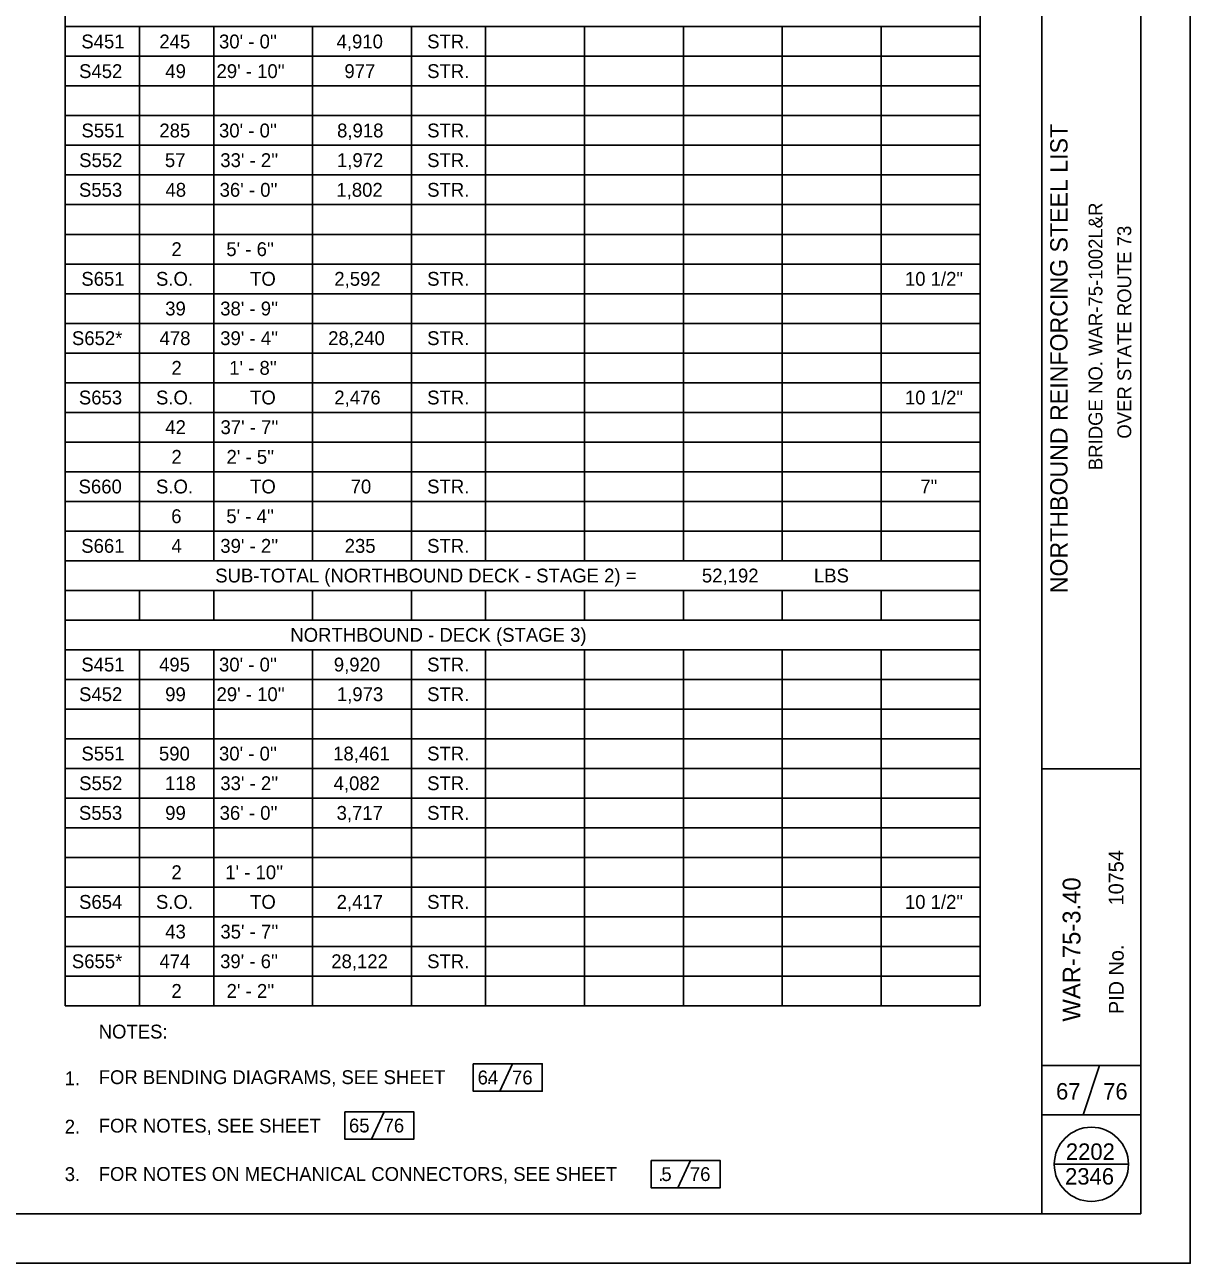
# Model space of a CAD drawing. Extents: x 1485751 to 1485785, y 230696.6 to 230718.6.
# Drawn here: x 1485773.25 to 1485785.03, y 230696.64 to 230709.16 of the extents above; entities that cross this region are included whole.
import ezdxf

# ---------------------------------------------------------------- set-up
doc = ezdxf.new("R2010")
doc.units = 0
for name, color, linetype in [('BR_P_Gen_Text', 7, 'Continuous'), ('BR_P_Sub_Text', 7, 'Continuous'), ('SH_Border', 7, 'Continuous'), ('SH_Cut_Line', 7, 'Continuous'), ('SH_Data', 7, 'Continuous'), ('TX_P_Misc', 7, 'Continuous')]:
    doc.layers.add(name, color=color, linetype=linetype)

msp = doc.modelspace()

# ---------------------------------------------------------------- linework, layer by layer
at = {"layer": 'BR_P_Gen_Text'}
for p, q in [((1485778.18, 230698.658), (1485778.052, 230698.38)), ((1485776.882, 230698.172), (1485776.753, 230697.894)), ((1485779.978, 230697.681), (1485779.85, 230697.403))]:
    msp.add_line(p, q, dxfattribs=at)
for points in [[(1485777.783, 230698.658), (1485778.48, 230698.658), (1485778.48, 230698.38), (1485777.783, 230698.38)], [(1485777.783, 230698.658), (1485778.48, 230698.658), (1485778.48, 230698.38), (1485777.783, 230698.38)], [(1485776.485, 230698.172), (1485777.181, 230698.172), (1485777.181, 230697.894), (1485776.485, 230697.894)], [(1485776.485, 230698.172), (1485777.181, 230698.172), (1485777.181, 230697.894), (1485776.485, 230697.894)], [(1485779.582, 230697.681), (1485780.278, 230697.681), (1485780.278, 230697.403), (1485779.582, 230697.403)], [(1485779.582, 230697.681), (1485780.278, 230697.681), (1485780.278, 230697.403), (1485779.582, 230697.403)]]:
    msp.add_lwpolyline(points, close=True, dxfattribs=at)
at = {"layer": 'SH_Border'}
for p, q in [((1485783.533, 230697.141), (1485783.533, 230718.141)), ((1485783.533, 230697.141), (1485783.533, 230718.141)), ((1485783.533, 230697.141), (1485783.533, 230718.141)), ((1485783.533, 230701.641), (1485784.533, 230701.641)), ((1485783.533, 230701.641), (1485784.533, 230701.641)), ((1485783.533, 230701.641), (1485784.533, 230701.641)), ((1485783.533, 230698.641), (1485784.533, 230698.641)), ((1485783.95, 230698.141), (1485784.116, 230698.641)), ((1485783.533, 230698.141), (1485784.533, 230698.141))]:
    msp.add_line(p, q, dxfattribs=at)
msp.add_lwpolyline([(1485753.033, 230718.141), (1485784.533, 230718.141), (1485784.533, 230697.141), (1485753.033, 230697.141)], close=True, dxfattribs=at)
at = {"layer": 'SH_Cut_Line'}
msp.add_lwpolyline([(1485751.033, 230718.641), (1485785.033, 230718.641), (1485785.033, 230696.641), (1485751.033, 230696.641)], close=True, dxfattribs=at)
at = {"layer": 'SH_Data'}
msp.add_line((1485783.658, 230697.641), (1485784.408, 230697.641), dxfattribs=at)
msp.add_line((1485783.658, 230697.641), (1485784.408, 230697.641), dxfattribs=at)
msp.add_line((1485783.658, 230697.641), (1485784.408, 230697.641), dxfattribs=at)
msp.add_circle((1485784.033, 230697.641), 0.375, dxfattribs=at)
at = {"layer": 'TX_P_Misc'}
for p, q in [((1485773.658, 230717.394), (1485773.658, 230699.244)), ((1485782.908, 230717.394), (1485782.908, 230699.244)), ((1485773.658, 230709.144), (1485782.908, 230709.144)), ((1485774.408, 230709.144), (1485774.408, 230703.744)), ((1485775.158, 230709.144), (1485775.158, 230703.744)), ((1485776.158, 230709.144), (1485776.158, 230703.744)), ((1485777.158, 230709.144), (1485777.158, 230703.744)), ((1485777.908, 230709.144), (1485777.908, 230703.744)), ((1485778.908, 230709.144), (1485778.908, 230703.744)), ((1485779.908, 230709.144), (1485779.908, 230703.744)), ((1485780.908, 230709.144), (1485780.908, 230703.744)), ((1485781.908, 230709.144), (1485781.908, 230703.744)), ((1485773.658, 230708.844), (1485782.908, 230708.844)), ((1485773.658, 230708.544), (1485782.908, 230708.544)), ((1485773.658, 230708.244), (1485782.908, 230708.244)), ((1485773.658, 230707.944), (1485782.908, 230707.944)), ((1485773.658, 230707.644), (1485782.908, 230707.644)), ((1485773.658, 230707.344), (1485782.908, 230707.344)), ((1485773.658, 230707.044), (1485782.908, 230707.044)), ((1485773.658, 230706.744), (1485782.908, 230706.744)), ((1485773.658, 230706.444), (1485782.908, 230706.444)), ((1485773.658, 230706.144), (1485782.908, 230706.144)), ((1485773.658, 230705.844), (1485782.908, 230705.844)), ((1485773.658, 230705.544), (1485782.908, 230705.544)), ((1485773.658, 230705.244), (1485782.908, 230705.244)), ((1485773.658, 230704.944), (1485782.908, 230704.944)), ((1485773.658, 230704.644), (1485782.908, 230704.644)), ((1485773.658, 230704.344), (1485782.908, 230704.344)), ((1485773.658, 230704.044), (1485782.908, 230704.044)), ((1485773.658, 230703.744), (1485782.908, 230703.744)), ((1485773.658, 230703.444), (1485782.908, 230703.444)), ((1485774.408, 230703.444), (1485774.408, 230703.144)), ((1485775.158, 230703.444), (1485775.158, 230703.144)), ((1485776.158, 230703.444), (1485776.158, 230703.144)), ((1485777.158, 230703.444), (1485777.158, 230703.144)), ((1485777.908, 230703.444), (1485777.908, 230703.144)), ((1485778.908, 230703.444), (1485778.908, 230703.144)), ((1485779.908, 230703.444), (1485779.908, 230703.144)), ((1485780.908, 230703.444), (1485780.908, 230703.144)), ((1485781.908, 230703.444), (1485781.908, 230703.144)), ((1485773.658, 230703.144), (1485782.908, 230703.144)), ((1485773.658, 230702.844), (1485782.908, 230702.844)), ((1485774.408, 230702.844), (1485774.408, 230699.244)), ((1485775.158, 230702.844), (1485775.158, 230699.244)), ((1485776.158, 230702.844), (1485776.158, 230699.244)), ((1485777.158, 230702.844), (1485777.158, 230699.244)), ((1485777.908, 230702.844), (1485777.908, 230699.244)), ((1485778.908, 230702.844), (1485778.908, 230699.244)), ((1485779.908, 230702.844), (1485779.908, 230699.244)), ((1485780.908, 230702.844), (1485780.908, 230699.244)), ((1485781.908, 230702.844), (1485781.908, 230699.244)), ((1485773.658, 230702.544), (1485782.908, 230702.544)), ((1485773.658, 230702.244), (1485782.908, 230702.244)), ((1485773.658, 230701.944), (1485782.908, 230701.944)), ((1485773.658, 230701.644), (1485782.908, 230701.644)), ((1485773.658, 230701.344), (1485782.908, 230701.344)), ((1485773.658, 230701.044), (1485782.908, 230701.044)), ((1485773.658, 230700.744), (1485782.908, 230700.744)), ((1485773.658, 230700.444), (1485782.908, 230700.444)), ((1485773.658, 230700.144), (1485782.908, 230700.144)), ((1485773.658, 230699.844), (1485782.908, 230699.844)), ((1485773.658, 230699.544), (1485782.908, 230699.544)), ((1485773.658, 230699.244), (1485782.908, 230699.244))]:
    msp.add_line(p, q, dxfattribs=at)

# ---------------------------------------------------------------- texts
at = {"layer": 'BR_P_Gen_Text'}
for s, p in [('64', (1485777.827, 230698.449)), ('76', (1485778.175, 230698.449)), ('65', (1485776.526, 230697.963)), ('76', (1485776.876, 230697.963)), ('5', (1485779.685, 230697.472)), ('76', (1485779.973, 230697.472))]:
    msp.add_text(s, height=0.14, dxfattribs=at).set_placement(p)
at = {"layer": 'BR_P_Sub_Text'}
msp.add_text('WAR-75-3.40', height=0.18, rotation=90, dxfattribs=at).set_placement((1485783.923, 230699.084))
at = {"layer": 'SH_Data'}
for s, height, p in [('     NORTHBOUND REINFORCING STEEL LIST    ', 0.175, (1485783.792, 230703.09)), ('BRIDGE NO. WAR-75-1002L&R', 0.14, (1485784.145, 230704.66)), ('OVER STATE ROUTE 73', 0.14, (1485784.436, 230704.978)), ('10754', 0.15, (1485784.358, 230700.259)), ('PID No.', 0.15, (1485784.36, 230699.16))]:
    msp.add_text(s, height=height, rotation=90, dxfattribs=at).set_placement(p)
for s, p in [('67', (1485783.676, 230698.296)), ('76', (1485784.152, 230698.296)), ('2202', (1485783.775, 230697.686)), ('2346', (1485783.767, 230697.436))]:
    msp.add_text(s, height=0.1666, dxfattribs=at).set_placement(p)
at = {"layer": 'TX_P_Misc'}
for s, p in [('S451', (1485773.82, 230708.924)), ('245', (1485774.609, 230708.924)), ("30' - 0''", (1485775.212, 230708.924)), ('4,910', (1485776.401, 230708.924)), ('STR.', (1485777.317, 230708.924)), ('S452', (1485773.797, 230708.624)), ('49', (1485774.669, 230708.624)), ("29' - 10''", (1485775.187, 230708.624)), ('977', (1485776.48, 230708.624)), ('STR.', (1485777.317, 230708.624)), ('S551', (1485773.821, 230708.024)), ('285', (1485774.609, 230708.024)), ("30' - 0''", (1485775.212, 230708.024)), ('8,918', (1485776.406, 230708.024)), ('STR.', (1485777.317, 230708.024)), ('S552', (1485773.798, 230707.724)), ('57', (1485774.665, 230707.724)), ("33' - 2''", (1485775.225, 230707.724)), ('1,972', (1485776.405, 230707.724)), ('STR.', (1485777.317, 230707.724)), ('S553', (1485773.796, 230707.424)), ('48', (1485774.671, 230707.424)), ("36' - 0''", (1485775.218, 230707.424)), ('1,802', (1485776.399, 230707.424)), ('STR.', (1485777.317, 230707.424)), ('2', (1485774.731, 230706.824)), ("5' - 6''", (1485775.286, 230706.824)), ('S651', (1485773.82, 230706.524)), ('S.O.', (1485774.575, 230706.524)), ('TO', (1485775.526, 230706.524)), ('2,592', (1485776.378, 230706.524)), ('STR.', (1485777.317, 230706.524)), (' 10 1/2"', (1485782.096, 230706.524)), ('39', (1485774.668, 230706.224)), ("38' - 9''", (1485775.224, 230706.224)), ('S652*', (1485773.725, 230705.924)), ('478', (1485774.611, 230705.924)), ("39' - 4''", (1485775.224, 230705.924)), ('28,240', (1485776.316, 230705.924)), ('STR.', (1485777.317, 230705.924)), ('2', (1485774.731, 230705.624)), ("1' - 8''", (1485775.315, 230705.624)), ('S653', (1485773.795, 230705.324)), ('S.O.', (1485774.575, 230705.324)), ('TO', (1485775.526, 230705.324)), ('2,476', (1485776.378, 230705.324)), ('STR.', (1485777.317, 230705.324)), (' 10 1/2"', (1485782.096, 230705.324)), ('42', (1485774.669, 230705.024)), ("37' - 7''", (1485775.227, 230705.024)), ('2', (1485774.731, 230704.724)), ("2' - 5''", (1485775.288, 230704.724)), ('S660', (1485773.792, 230704.424)), ('S.O.', (1485774.575, 230704.424)), ('TO', (1485775.526, 230704.424)), ('70', (1485776.543, 230704.424)), ('STR.', (1485777.317, 230704.424)), (' 7"', (1485782.252, 230704.424)), ('6', (1485774.729, 230704.124)), ("5' - 4''", (1485775.286, 230704.124)), ('S661', (1485773.819, 230703.824)), ('4', (1485774.731, 230703.824)), ("39' - 2''", (1485775.225, 230703.824)), ('235', (1485776.483, 230703.824)), ('STR.', (1485777.317, 230703.824)), ('SUB-TOTAL (NORTHBOUND DECK - STAGE 2) =', (1485775.174, 230703.524)), ('52,192', (1485780.095, 230703.524)), ('LBS', (1485781.228, 230703.524)), ('NORTHBOUND - DECK (STAGE 3)', (1485775.933, 230702.924)), ('S451', (1485773.82, 230702.624)), ('495', (1485774.606, 230702.624)), ("30' - 0''", (1485775.212, 230702.624)), ('9,920', (1485776.373, 230702.624)), ('STR.', (1485777.317, 230702.624)), ('S452', (1485773.797, 230702.324)), ('99', (1485774.668, 230702.324)), ("29' - 10''", (1485775.187, 230702.324)), ('1,973', (1485776.404, 230702.324)), ('STR.', (1485777.317, 230702.324)), ('S551', (1485773.821, 230701.724)), ('590', (1485774.605, 230701.724)), ("30' - 0''", (1485775.212, 230701.724)), ('18,461', (1485776.366, 230701.724)), ('STR.', (1485777.317, 230701.724)), ('S552', (1485773.798, 230701.424)), ('118', (1485774.666, 230701.424)), ("33' - 2''", (1485775.225, 230701.424)), ('4,082', (1485776.371, 230701.424)), ('STR.', (1485777.317, 230701.424)), ('S553', (1485773.796, 230701.124)), ('99', (1485774.668, 230701.124)), ("36' - 0''", (1485775.218, 230701.124)), ('3,717', (1485776.401, 230701.124)), ('STR.', (1485777.317, 230701.124)), ('2', (1485774.731, 230700.524)), ("1' - 10''", (1485775.275, 230700.524)), ('S654', (1485773.797, 230700.224)), ('S.O.', (1485774.575, 230700.224)), ('TO', (1485775.526, 230700.224)), ('2,417', (1485776.402, 230700.224)), ('STR.', (1485777.317, 230700.224)), (' 10 1/2"', (1485782.096, 230700.224)), ('43', (1485774.668, 230699.924)), ("35' - 7''", (1485775.226, 230699.924)), ('S655*', (1485773.724, 230699.624)), ('474', (1485774.61, 230699.624)), ("39' - 6''", (1485775.223, 230699.624)), ('28,122', (1485776.347, 230699.624)), ('STR.', (1485777.317, 230699.624)), ('2', (1485774.731, 230699.324)), ("2' - 2''", (1485775.289, 230699.324)), ('NOTES:', (1485773.995, 230698.913)), ('1.', (1485773.652, 230698.44)), ('FOR BENDING DIAGRAMS, SEE SHEET        .', (1485773.995, 230698.452)), ('2.', (1485773.652, 230697.952)), ('FOR NOTES, SEE SHEET        .', (1485773.995, 230697.962)), ('3.', (1485773.652, 230697.472)), ('FOR NOTES ON MECHANICAL CONNECTORS, SEE SHEET        .', (1485773.995, 230697.473))]:
    msp.add_text(s, height=0.14, dxfattribs=at).set_placement(p)

doc.saveas('drawing.dxf')
